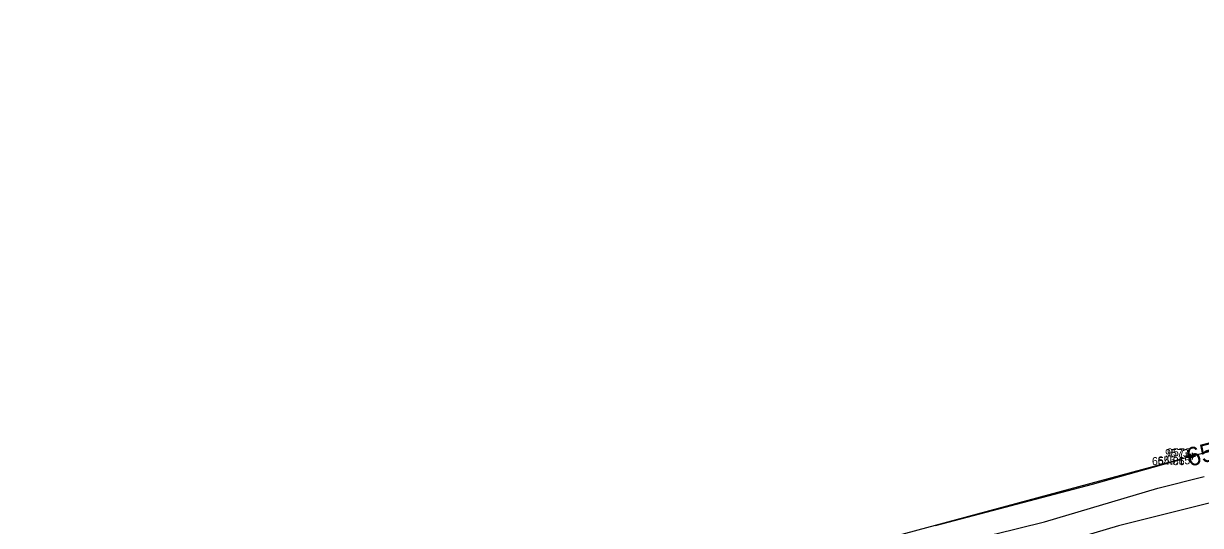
# Model space of a CAD drawing. Extents: x 2129350 to 2137777, y 657588 to 659885.
# Drawn here: x 2134710.2 to 2134886.7, y 659312.2 to 659387.5 of the extents above; entities that cross this region are included whole.
import ezdxf

# ---------------------------------------------------------------- set-up
doc = ezdxf.new("R2010")
doc.units = 0
for name, color, linetype in [('DT_X_Contour_Major', 7, 'Continuous'), ('DT_X_Contour_Minor', 7, 'Continuous'), ('DT_X_TIN_Hull', 7, 'Continuous'), ('SV_X_Shot_Marker', 7, 'Continuous'), ('SV_X_Text_Elevation', 7, 'Continuous'), ('SV_X_Text_Name', 7, 'Continuous')]:
    doc.layers.add(name, color=color, linetype=linetype)

msp = doc.modelspace()

# ---------------------------------------------------------------- linework, layer by layer
at = {"layer": 'DT_X_Contour_Major'}
msp.add_lwpolyline([(2134846.97, 659312.24), (2134870.49, 659318.41), (2134883.7, 659322.1)], dxfattribs=at)
at = {"layer": 'DT_X_Contour_Minor'}
for points in [[(2134699.42, 659268.63), (2134712.76, 659272.09), (2134713.84, 659272.45), (2134717.95, 659274.17), (2134736.51, 659279.04), (2134742.02, 659280.41), (2134759.71, 659285.04), (2134766.23, 659286.82), (2134783.58, 659291.38), (2134789.78, 659293.07), (2134791.58, 659293.55), (2134798.46, 659295.31), (2134815.72, 659299.91), (2134823.16, 659301.82), (2134839.85, 659306.26), (2134840.98, 659306.55), (2134855.81, 659310.93), (2134863.28, 659312.79), (2134880.29, 659317.84), (2134887.25, 659319.57)], [(2134889.82, 659316.01), (2134874.38, 659312.18), (2134865.67, 659309.6), (2134850.17, 659305.74), (2134842.4, 659303.44), (2134840.18, 659302.87), (2134831.43, 659300.54), (2134816.01, 659296.59), (2134806.93, 659294.17), (2134791.84, 659290.31), (2134790.89, 659290.05), (2134777.18, 659286.32), (2134768.19, 659283.96), (2134753, 659279.82), (2134744.06, 659277.47), (2134730.43, 659274.1), (2134720.3, 659271.44), (2134709.4, 659266.88)]]:
    msp.add_lwpolyline(points, dxfattribs=at)
at = {"layer": 'DT_X_TIN_Hull'}
msp.add_lwpolyline([(2135530.59, 659503.78), (2135475.39, 659489.05), (2135416.67, 659473.77), (2135375.74, 659461.35), (2135332.28, 659448.99), (2135282.8, 659433.85), (2135234.45, 659419.66), (2135187.99, 659405.62), (2135140.1, 659391.95), (2135093.39, 659377.69), (2135039.16, 659363.4), (2134946.54, 659338.8), (2134928.12, 659333.86), (2134885.43, 659322.6), (2134839.28, 659310.17), (2134788.72, 659297.4), (2134742.32, 659285.27), (2134695.66, 659270.22), (2134671.45, 659264.13), (2134637.39, 659257.64), (2134592.77, 659246.33), (2134552.01, 659235.92), (2134498.13, 659222.44), (2134448.36, 659209.51)], dxfattribs=at)
at = {"layer": 'SV_X_Shot_Marker'}
for p, q in [((2134884.64, 659322.48), (2134885.64, 659322.48)), ((2134884.93, 659322.6), (2134885.93, 659322.6)), ((2134885.14, 659322.98), (2134885.14, 659321.98)), ((2134885.14, 659322.48), (2134885.14, 659322.48)), ((2134885.43, 659323.1), (2134885.43, 659322.1)), ((2134885.43, 659322.6), (2134885.43, 659322.6))]:
    msp.add_line(p, q, dxfattribs=at)

# ---------------------------------------------------------------- texts
at = {"layer": 'DT_X_Contour_Major'}
msp.add_text('655', height=2.8, rotation=14.7351, dxfattribs=at).set_placement((2134885.02, 659321.01))
at = {"layer": 'SV_X_Text_Elevation'}
for s, p in [('654.86', (2134879.41, 659321.28)), ('655.15', (2134880.26, 659321.4))]:
    msp.add_text(s, height=1.2, dxfattribs=at).set_placement(p)
at = {"layer": 'SV_X_Text_Name'}
for s, p in [('9573', (2134881.37, 659322.48)), ('9572', (2134881.67, 659322.6))]:
    msp.add_text(s, height=1.2, dxfattribs=at).set_placement(p)

doc.saveas('drawing.dxf')
